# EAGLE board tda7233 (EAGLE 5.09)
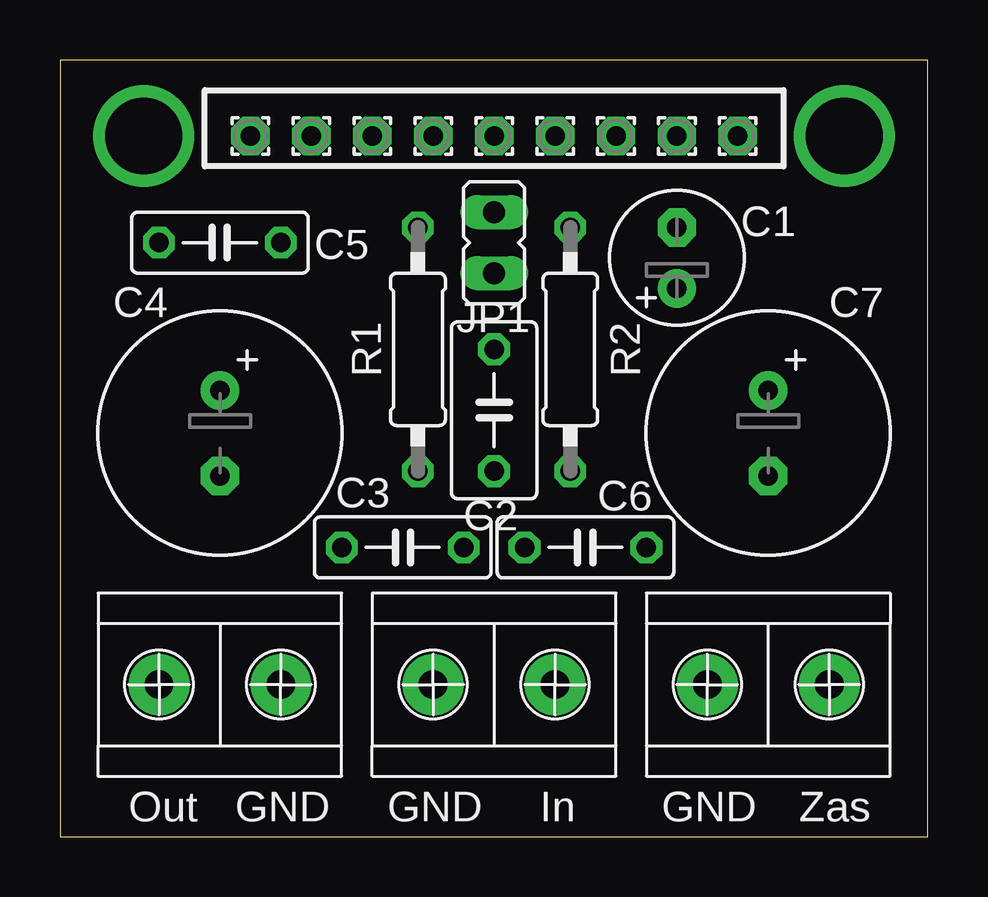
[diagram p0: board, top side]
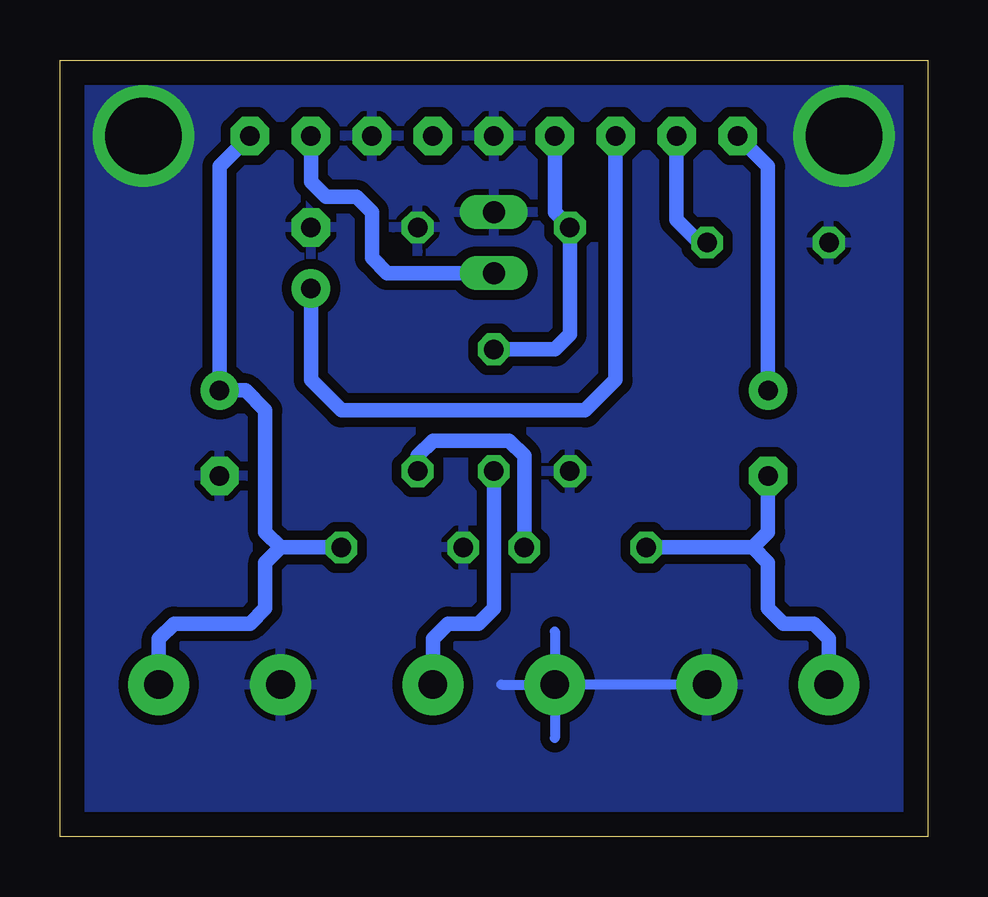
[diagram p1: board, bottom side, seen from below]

Size 36.18 x 32.37 mm. Coordinates in mm from the lower left corner, seen from the top.
Outline: 0,0 36.18,0 36.18,32.37 0,32.37 0,0
Copper layers (1*16): Top 0.035mm / dielectric 1.5mm / Bottom 0.035mm
Design rules "default": minimum track width 10mil, minimum drill 24mil, track to track 8mil, track to pad 8mil, pad to pad 8mil, via to via 8mil, smd to smd 8mil, copper to edge 40mil, drill to drill 8mil, minimum pad ring 10mil, minimum via ring 8mil, stop-mask expansion 4mil, vias tented up to drill 0mil, thermal gap 10mil

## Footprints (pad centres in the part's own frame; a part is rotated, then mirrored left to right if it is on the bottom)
E2,5-6 = drill 0.813 pad 1.6 round: + -1.27,0 | drill 0.813 pad 1.6 octagon: - 1.27,0
C050-035X075 = drill 0.813 octagon: 1 -2.54,0; 2 2.54,0
C050-025X075 = drill 0.813 octagon: 1 -2.54,0; 2 2.54,0
E3,5-10 = drill 0.813 pad 1.6 round: + -1.778,0 | drill 0.813 pad 1.6 octagon: - 1.778,0
JP1 = drill 0.914 long: 1 0,-1.27; 2 0,1.27
1,6/0,8 = drill 0.813 pad 1.6 octagon: 1 0,0
0207/10 = drill 0.813 octagon: 1 -5.08,0; 2 5.08,0
ARK2 = drill 1.2 pad 2.54 round: 1 -2.54,0; 3 2.54,0 | drill 0.8 pad 2.54 round: 2 2.54,0

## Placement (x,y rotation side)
C1  [E2,5-6]  25.72,24.13 90 top
C2  [C050-035X075]  18.1,17.78 90 top
C3  [C050-025X075]  14.29,12.06 0 top
C4  [E3,5-10]  6.67,16.83 270 top
C5  [C050-025X075]  6.67,24.77 180 top
C6  [C050-025X075]  21.91,12.06 180 top
C7  [E3,5-10]  29.53,16.83 270 top
JP1  [JP1]  18.1,24.77 0 top
PAD1  [1,6/0,8]  7.94,29.21 90 top
PAD2  [1,6/0,8]  10.48,29.21 90 top
PAD3  [1,6/0,8]  13.02,29.21 90 top
PAD4  [1,6/0,8]  15.56,29.21 90 top
PAD5  [1,6/0,8]  18.1,29.21 90 top
PAD6  [1,6/0,8]  20.64,29.21 90 top
PAD7  [1,6/0,8]  23.18,29.21 90 top
PAD8  [1,6/0,8]  25.72,29.21 90 top
PAD9  [1,6/0,8]  28.26,29.21 90 top
R1  [0207/10]  14.92,20.32 90 top
R2  [0207/10]  21.27,20.32 270 top
U$1  ARK2  [ARK2]  18.1,6.35 180 top
U$2  ARK2  [ARK2]  6.67,6.35 180 top
U$3  ARK2  [ARK2]  29.53,6.35 0 top

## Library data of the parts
C1-C7 R1 R2 = rcl
JP1 = jumper
PAD1-PAD9 = wirepad
U$1-U$3 = ark2

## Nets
GND: C1.- C5.2 C6.2 C7.- JP1.2 PAD5.1 PAD7.1 R1.1 R2.1 U$1.2 U$2.1 U$3.1
N$1: C1.+ PAD3.1
N$2: C2.2 PAD4.1 R1.2
N$3: C3.2 R2.2
N$4: C4.+ PAD1.1
N$5: C3.1 C4.- U$2.2
N$6: JP1.1 PAD8.1
N$7: C5.1 PAD2.1
N$8: C6.1 C7.+ PAD9.1 U$3.2
N$9: C2.1 U$1.1

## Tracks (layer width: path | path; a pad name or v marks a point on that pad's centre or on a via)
GND  (via drill 3.2)
  Bottom 0.406: U$2.1 U$1.2 17.78,6.35
  other vias: 3.49,29.21 32.7,29.21
  pour Bottom (isolate 0.406): -0.95,33.02 37.15,33.02 37.15,-0.63 -0.95,-0.63
N$1
  Bottom 0.61: PAD3.1 13.02,19.05 14.29,17.78 24.45,17.78 25.72,19.05 C1.+
N$2
  Bottom 0.61: PAD4.1 15.56,26.03 R1.2 14.92,20.95 15.56,20.32 C2.2
N$3
  Bottom 0.61: R2.2 21.27,15.88 20.64,16.51 17.46,16.51 16.83,15.88 C3.2
N$4
  Bottom 0.61: C4.+ 6.67,27.94 PAD1.1
N$5
  Bottom 0.61: 7.3,12.06 6.67,12.7 C4.- | 7.3,12.06 C3.1 | 7.3,12.06 6.67,11.43 6.67,9.52 6.03,8.89 4.76,8.89 4.13,8.26 U$2.2
N$6
  Bottom 0.61: JP1.1 22.54,23.49 23.18,24.13 23.18,26.03 23.81,26.67 25.08,26.67 25.72,27.3 PAD8.1
N$7
  Bottom 0.61: C5.1 9.53,24.77 10.48,25.72 PAD2.1
N$8
  Bottom 0.61: PAD9.1 29.53,27.94 C7.+ 28.45,18.6 27.62,17.78 27.62,12.7 26.99,12.06 | 26.99,12.06 C6.1 | 26.99,12.06 27.62,11.43 27.62,9.52 28.26,8.89 31.43,8.89 32.07,8.26 U$3.2
N$9
  Bottom 0.61: C2.1 18.1,9.52 18.73,8.89 20,8.89 20.64,8.26 U$1.1
N$10
  Bottom 0.406: 15.56,8.57 15.56,4.13

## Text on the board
tPlace: Out | GND | GND | In | GND | Zas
